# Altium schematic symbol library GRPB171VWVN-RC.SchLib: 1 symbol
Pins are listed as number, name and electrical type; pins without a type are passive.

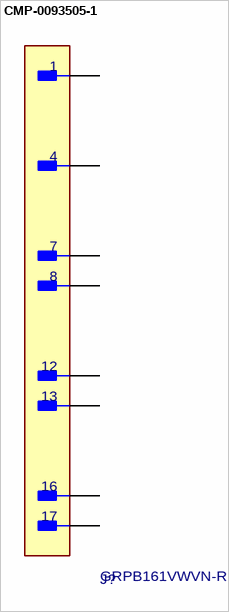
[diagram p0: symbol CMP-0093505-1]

## CMP-0093505-1
designator J?, comment GRPB161VWVN-RC
Connector Header Through Hole 16 position 0.050" (1.27mm); Manufacturer: Sullins; Current_A: 1A; Conn Gender: Male; Conn Orientation: Straight; AEC Qualified: No; ContactFinish: Gold,Nickel; Row_Count: 1; SizeZ_mm: 4.4mm
footprint FP-GRPB161VWVN-RC_HDR16-MFG
pins: 1, 4, 7, 8, 12, 13, 16, 17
